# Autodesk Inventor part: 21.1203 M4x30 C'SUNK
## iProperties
Created: 2006-12
Part Number: 21.1203 M4x30 C'SUNK
Material: Steel, Mild
Description: Hexagon socket countersunk head cap screws
Document SubType Name: Modeling
Standard: DIN 7991
Designer: Andy Moles
Standards Organization: DIN
Language: en-US
Size Designation: M4x30
Categories: <MemberInstance Version="R10.0.0"><Categories><Category DisplayName="Fasteners" InternalName="e4da775c-781d-43d5-af7c-5136215cf5a6" Mnemonic="FSTN"><Category Di
Density: 7.86 g/cm^3
Mass: 3.23325 g
Surface Area: 4.84524 cm^2
Volume: 0.411354 cm^3
Author: Andy Moles
Revision Number: 1
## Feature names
1. Revolution1
2. Extrusion1
3. Fillet1
4. Chamfer1
